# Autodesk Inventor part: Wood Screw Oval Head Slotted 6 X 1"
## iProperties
Shininess: 28.0
Length Units: 11272
Angle Units: 11279
Time Units: 11290
Mass Units: 11286
Length Display Precision: 4
Angle Display Precision: 2
Compacted: True
Category: Fasteners
Created: 2005-10
Part Number: Wood Screw Oval Head Slotted 6 X 1"
Material: Steel, Carbon
Description: Wood Screw Oval Head Slotted
Document SubType Name: Modeling
Designer: JDP
Density: 7.84
Volumn: 0.0334175022831377
Area: 0.7931629180511741
PropertySet Name: Model Information
Control State: 0
Master: False
Checked Out: False
SUB-ASSEMBLY: HARDWARE
MATERIAL NAME: Wood Screw Oval Head Slotted 6 X 1"
MATERIAL TYPE: Other Item
Author: Joshua Petitt
Comments: A basic wood screw.  NO GUARANTEES ARE MADE ABOUT THE ACCURACY OF THE PART MODEL OR TABLE.  USE AT YOUR OWN RISK.
Revision Number: A
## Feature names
1. Revolution1
2. slot [Extrusion]
3. Coil1
4. Coil2
